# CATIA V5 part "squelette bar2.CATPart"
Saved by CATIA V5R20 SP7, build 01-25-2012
Part number: squelette bar2
Publications: "Plan.1", "Point.1", "Point.2", "Droite.1", "Droite.2", "Droite.3"
Bounding box of the stored display mesh (mm): x 0 to 160, y 0 to 40, z 0 to 0
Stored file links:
  D:\thinkmotion-MPB\Dropbox\Pack 1 sylvain\CFAO_2010_yyang\yyang\CFAO_2010_yyang\squelette bar2.CATPart
  D:\thinkmotion-MPB\Dropbox\Pack 1 sylvain\CFAO_2010_yyang\yyang\CFAO_2010_yyang\yyang.CATProduct
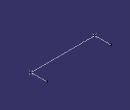
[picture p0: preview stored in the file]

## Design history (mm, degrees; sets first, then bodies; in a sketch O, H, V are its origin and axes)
External parameters (linked from other documents)
  `External.Longueur du bar` = 160 mm
Body1 (main body)
  Plane1: type Offset, RefPlane zx-plane, Offset 0
  Point1: (0, 0, 0)
  Point2: (160 {= `External.Longueur du bar`}, 0, 0)
  Line1: type PtDir, RefPoint Point1, Direction (0, 1, 0), Start 0, End 40
  Line2: type PtDir, RefPoint Point2, Direction (0, 1, 0), Start 0, End 40
  Line3: type PtPt, FirstPoint Point1, SecondPoint Point2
